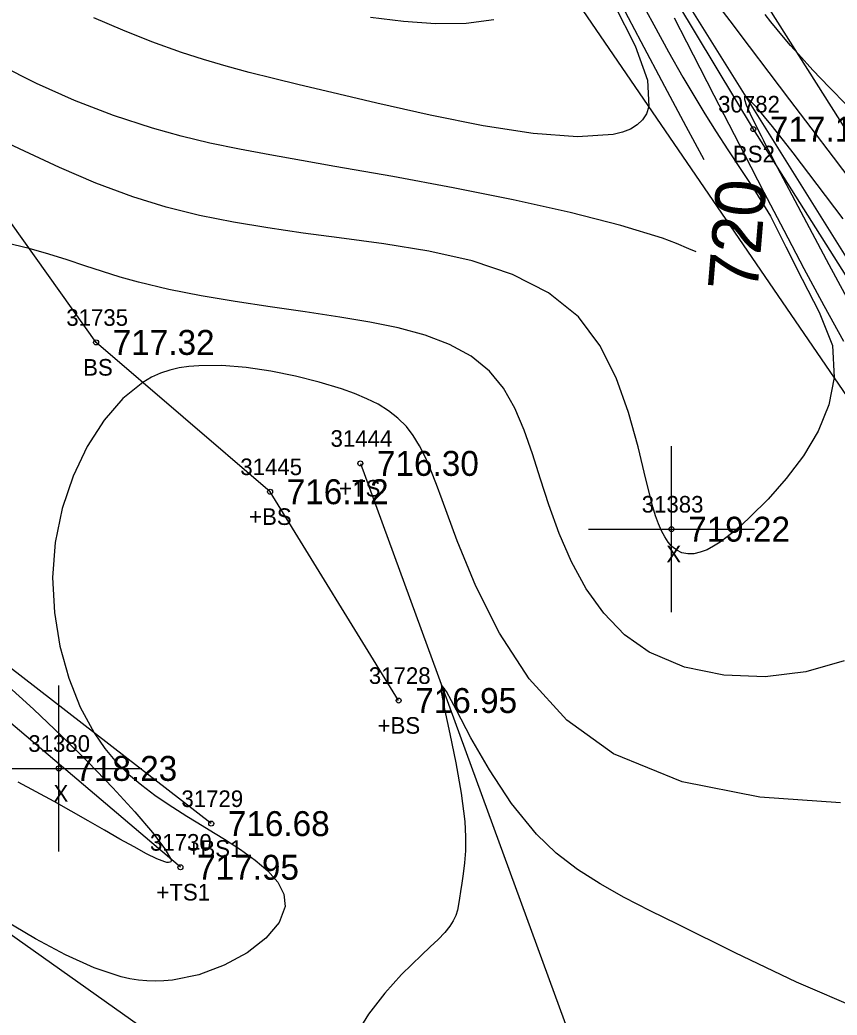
# Model space of a CAD drawing. Extents: x 1376587 to 1378239, y 1000335 to 1003031.
# Drawn here: x 1377060.9 to 1377110.1, y 1001997.9 to 1002057.8 of the extents above; entities that cross this region are included whole.
import ezdxf

# ---------------------------------------------------------------- set-up
doc = ezdxf.new("R2010")
doc.units = 0
for name, color, linetype in [('RD_DTM_BkLn2', 7, 'Continuous'), ('RD_DTM_BkLn_txCode', 7, 'Continuous'), ('RD_DTM_Major1', 7, 'Continuous'), ('RD_DTM_Major1_Lbl', 7, 'Continuous'), ('RD_DTM_Minor1', 7, 'Continuous'), ('RD_EX_H2O', 7, 'Continuous'), ('RD_EX_Misc', 7, 'Continuous'), ('RD_EX_Misc_txCode', 7, 'Continuous'), ('RD_EX_TX_Misc_ELEV', 7, 'Continuous'), ('RD_SMD_Locator', 7, 'Continuous')]:
    doc.layers.add(name, color=color, linetype=linetype)

msp = doc.modelspace()

# ---------------------------------------------------------------- linework, layer by layer
at = {"layer": 'RD_DTM_BkLn2'}
msp.add_line((1377081.372, 1002031.089), (1377098.323, 1001984.744), dxfattribs=at)
for points in [[(1377142.847, 1002000.419), (1377120.857, 1002035.022), (1377093.975, 1002077.46), (1377068.464, 1002119.505), (1377041.306, 1002163.638), (1377022.11, 1002198.969), (1376992.664, 1002247.269), (1376968.66, 1002290.747), (1376938.21, 1002335.497), (1376936.932, 1002336.502), (1376934.733, 1002336.167)], [(1376931.277, 1002334.72), (1376930.538, 1002327.778), (1376948.096, 1002284.738), (1376977.707, 1002235.156), (1376998.585, 1002198.065), (1377023.427, 1002151.701), (1377053.922, 1002110.488), (1377069.919, 1002089.279), (1377076.048, 1002081.264), (1377085.906, 1002071.338), (1377113.825, 1002030.519), (1377124.485, 1002013.092), (1377135.759, 1001990.148)], [(1376935.374, 1002334.231), (1376953.076, 1002295.685), (1376977.004, 1002261.504), (1376998.814, 1002228.831), (1377019.729, 1002192.044), (1377041.392, 1002156.493), (1377062.715, 1002120.197), (1377083.309, 1002087.295), (1377105.033, 1002051.213), (1377126.385, 1002017.412), (1377141.025, 1001985.591), (1377143.73, 1001977.344), (1377160.135, 1001942.462), (1377172.58, 1001925.323), (1377184.431, 1001906.97)], [(1377083.678, 1002016.815), (1377075.938, 1002029.384), (1377065.46, 1002038.372), (1377052.271, 1002056.869), (1377042.811, 1002066.409), (1377033.979, 1002056.948), (1377025.546, 1002060.176), (1377009.284, 1002065.352)], [(1377072.391, 1002009.404), (1377053.266, 1002024.229), (1377030.498, 1002041.755), (1377013.412, 1002051.132)], [(1377070.54, 1002006.776), (1377051.937, 1002022.56), (1377028.67, 1002037.413), (1377011.364, 1002045.988)], [(1377092.351, 1001980.005), (1377043.936, 1002014.334), (1377027.822, 1002012.65)]]:
    msp.add_lwpolyline(points, dxfattribs=at)
at = {"layer": 'RD_DTM_Major1'}
for points in [[(1377096.738, 1002059.39), (1377098.269, 1002056.482), (1377099.693, 1002053.79), (1377100.976, 1002051.381), (1377102.049, 1002049.39)], [(1377101.587, 1002043.829), (1377101.154, 1002044.013), (1377100.415, 1002044.318), (1377099.559, 1002044.641), (1377097.054, 1002045.418), (1377094.001, 1002046.193), (1377090.576, 1002046.95), (1377086.957, 1002047.676), (1377083.319, 1002048.354), (1377079.841, 1002048.97), (1377077.825, 1002049.318), (1377075.915, 1002049.655), (1377074.087, 1002050), (1377072.317, 1002050.37), (1377070.582, 1002050.785), (1377068.858, 1002051.263), (1377066.499, 1002052.038), (1377064.156, 1002052.944), (1377061.867, 1002053.959), (1377059.673, 1002055.063), (1377057.612, 1002056.235), (1377055.725, 1002057.453), (1377055.068, 1002057.919)]]:
    msp.add_lwpolyline(points, dxfattribs=at)
at = {"layer": 'RD_DTM_Minor1'}
for points in [[(1377098.119, 1002059.206), (1377099.038, 1002057.482), (1377099.923, 1002055.868), (1377100.792, 1002054.342), (1377101.453, 1002053.228), (1377102.121, 1002052.137), (1377102.804, 1002051.054), (1377103.508, 1002049.964), (1377104.24, 1002048.851), (1377105.007, 1002047.701), (1377106.067, 1002045.963), (1377106.995, 1002044.133), (1377107.981, 1002042.186), (1377108.995, 1002040.186), (1377109.804, 1002038.186), (1377109.901, 1002036.256), (1377109.579, 1002034.611), (1377108.936, 1002033.034), (1377108.054, 1002031.548), (1377107.02, 1002030.175), (1377105.919, 1002028.939), (1377104.834, 1002027.863), (1377104.353, 1002027.418), (1377103.894, 1002027.017), (1377103.455, 1002026.661), (1377103.035, 1002026.353), (1377102.633, 1002026.097), (1377102.249, 1002025.895), (1377101.838, 1002025.736), (1377101.448, 1002025.651), (1377101.081, 1002025.641), (1377100.737, 1002025.711), (1377100.418, 1002025.861), (1377100.124, 1002026.095), (1377099.902, 1002026.35), (1377099.696, 1002026.663), (1377099.503, 1002027.032), (1377099.322, 1002027.456), (1377099.151, 1002027.934), (1377098.986, 1002028.465), (1377098.556, 1002030.147), (1377098.093, 1002032.086), (1377097.525, 1002034.158), (1377096.784, 1002036.235), (1377095.799, 1002038.193), (1377094.498, 1002039.905), (1377092.695, 1002041.366), (1377090.534, 1002042.467), (1377088.104, 1002043.278), (1377085.494, 1002043.87), (1377082.793, 1002044.311), (1377080.089, 1002044.674), (1377077.924, 1002044.959), (1377075.809, 1002045.262), (1377073.734, 1002045.606), (1377071.692, 1002046.017), (1377069.673, 1002046.517), (1377067.67, 1002047.132), (1377065.448, 1002047.965), (1377063.263, 1002048.902), (1377061.145, 1002049.878), (1377059.122, 1002050.825)], [(1377111.549, 1002047.303), (1377109.863, 1002049.523), (1377108.521, 1002051.29), (1377107.235, 1002052.985), (1377105.997, 1002054.617), (1377104.803, 1002056.194), (1377103.644, 1002057.727), (1377102.515, 1002059.223)], [(1377096.661, 1002058.719), (1377097.929, 1002056.233), (1377098.661, 1002054.153), (1377098.738, 1002052.577), (1377098.597, 1002052.139), (1377098.366, 1002051.77), (1377098.047, 1002051.465), (1377097.643, 1002051.22), (1377097.156, 1002051.032), (1377096.591, 1002050.894), (1377094.449, 1002050.752), (1377091.784, 1002050.953), (1377088.767, 1002051.412), (1377085.568, 1002052.045), (1377082.358, 1002052.767), (1377079.308, 1002053.492), (1377077.68, 1002053.883), (1377076.144, 1002054.259), (1377074.686, 1002054.63), (1377073.288, 1002055.007), (1377071.934, 1002055.402), (1377070.607, 1002055.826), (1377068.82, 1002056.463), (1377067.06, 1002057.164), (1377065.331, 1002057.916)], [(1377089.414, 1002057.8), (1377087.739, 1002057.577), (1377085.901, 1002057.551), (1377083.962, 1002057.684), (1377081.985, 1002057.939)], [(1377100.27, 1002057.918), (1377101.011, 1002056.467), (1377101.81, 1002054.907), (1377102.66, 1002053.249), (1377103.558, 1002051.503), (1377104.498, 1002049.678), (1377105.663, 1002047.425), (1377106.862, 1002045.125), (1377108.075, 1002042.83), (1377109.282, 1002040.59), (1377110.465, 1002038.455)], [(1377110.667, 1002052.657), (1377109.61, 1002053.735), (1377108.624, 1002054.768), (1377107.744, 1002055.723), (1377107.277, 1002056.249), (1377106.853, 1002056.743), (1377106.463, 1002057.212), (1377106.098, 1002057.665), (1377105.748, 1002058.111)], [(1377110.443, 1002045.807), (1377108.887, 1002047.873), (1377107.435, 1002049.776), (1377106.181, 1002051.377), (1377105.216, 1002052.54), (1377104.631, 1002053.127), (1377104.501, 1002053.161), (1377104.499, 1002053.003), (1377104.61, 1002052.669), (1377104.822, 1002052.18), (1377105.122, 1002051.555), (1377105.496, 1002050.812), (1377105.641, 1002050.528), (1377105.794, 1002050.233), (1377105.954, 1002049.925), (1377106.121, 1002049.605), (1377106.296, 1002049.272), (1377106.477, 1002048.927), (1377107.902, 1002046.231), (1377109.588, 1002043.066), (1377111.467, 1002039.566)], [(1377110.5, 1002019.209), (1377108.202, 1002018.542), (1377105.742, 1002018.244), (1377103.257, 1002018.331), (1377100.883, 1002018.817), (1377098.758, 1002019.72), (1377097.276, 1002020.774), (1377096.025, 1002022.068), (1377094.973, 1002023.548), (1377094.092, 1002025.165), (1377093.352, 1002026.864), (1377092.723, 1002028.594), (1377092.22, 1002030.15), (1377091.739, 1002031.66), (1377091.237, 1002033.093), (1377090.668, 1002034.421), (1377089.99, 1002035.613), (1377089.156, 1002036.641), (1377088.05, 1002037.542), (1377086.744, 1002038.253), (1377085.27, 1002038.809), (1377083.658, 1002039.244), (1377081.939, 1002039.593), (1377080.144, 1002039.892), (1377078.052, 1002040.206), (1377075.939, 1002040.514), (1377073.841, 1002040.832), (1377071.795, 1002041.174), (1377069.837, 1002041.555), (1377068.005, 1002041.99), (1377066.901, 1002042.306), (1377065.836, 1002042.641), (1377064.784, 1002042.99), (1377063.717, 1002043.342), (1377062.608, 1002043.69), (1377061.428, 1002044.026), (1377059.473, 1002044.497)], [(1377110.279, 1002010.656), (1377105.43, 1002010.989), (1377100.756, 1002011.92), (1377096.624, 1002013.598), (1377093.806, 1002015.635), (1377091.541, 1002018.117), (1377089.743, 1002020.863), (1377088.327, 1002023.695), (1377087.21, 1002026.431), (1377086.306, 1002028.891), (1377085.96, 1002029.826), (1377085.624, 1002030.678), (1377085.288, 1002031.45), (1377084.937, 1002032.145), (1377084.559, 1002032.764), (1377084.141, 1002033.311), (1377083.636, 1002033.822), (1377083.07, 1002034.263), (1377082.446, 1002034.647), (1377081.763, 1002034.985), (1377081.023, 1002035.289), (1377080.227, 1002035.57), (1377078.891, 1002035.979), (1377077.463, 1002036.344), (1377075.983, 1002036.645), (1377074.493, 1002036.863), (1377073.033, 1002036.978), (1377071.645, 1002036.971), (1377071.041, 1002036.921), (1377070.458, 1002036.833), (1377069.892, 1002036.701), (1377069.34, 1002036.517), (1377068.8, 1002036.274), (1377068.267, 1002035.964), (1377067.072, 1002034.988), (1377065.946, 1002033.682), (1377064.93, 1002032.104), (1377064.07, 1002030.313), (1377063.408, 1002028.365), (1377062.987, 1002026.32), (1377062.838, 1002024.214), (1377062.947, 1002022.119), (1377063.283, 1002020.086), (1377063.814, 1002018.166), (1377064.508, 1002016.412), (1377065.335, 1002014.874), (1377065.994, 1002013.923), (1377066.697, 1002013.092), (1377067.438, 1002012.361), (1377068.208, 1002011.71), (1377069, 1002011.121), (1377069.806, 1002010.574), (1377070.366, 1002010.212), (1377070.93, 1002009.858), (1377071.495, 1002009.508), (1377072.63, 1002008.812), (1377073.198, 1002008.459), (1377074.146, 1002007.848), (1377075.036, 1002007.214), (1377075.809, 1002006.556), (1377076.407, 1002005.87), (1377076.773, 1002005.156), (1377076.846, 1002004.411), (1377076.484, 1002003.458), (1377075.686, 1002002.513), (1377074.549, 1002001.635), (1377073.168, 1002000.881), (1377071.639, 1002000.31), (1377070.058, 1001999.981), (1377069.541, 1001999.934), (1377069.027, 1001999.92), (1377068.515, 1001999.938), (1377068.003, 1001999.987), (1377067.491, 1002000.067), (1377066.975, 1002000.178), (1377065.334, 1002000.714), (1377063.624, 1002001.497), (1377061.819, 1002002.478), (1377059.89, 1002003.606)], [(1377059.971, 1002017.855), (1377061.682, 1002016.304), (1377063.397, 1002014.676), (1377064.981, 1002013.101), (1377066.47, 1002011.552), (1377067.787, 1002010.113), (1377068.857, 1002008.866), (1377069.605, 1002007.892), (1377069.953, 1002007.274), (1377069.97, 1002007.178), (1377069.953, 1002007.112), (1377069.906, 1002007.074), (1377069.829, 1002007.062), (1377069.724, 1002007.073), (1377069.593, 1002007.106), (1377069.122, 1002007.29), (1377068.497, 1002007.595), (1377067.745, 1002007.998), (1377066.891, 1002008.477), (1377065.96, 1002009.01), (1377064.978, 1002009.574), (1377063.966, 1002010.15), (1377062.928, 1002010.732), (1377061.859, 1002011.314), (1377060.76, 1002011.894)], [(1377111.462, 1001998.213), (1377107.641, 1001999.856), (1377103.942, 1002001.629), (1377100.51, 1002003.334), (1377098.832, 1002004.162), (1377097.266, 1002004.96), (1377095.804, 1002005.774), (1377094.44, 1002006.649), (1377093.169, 1002007.631), (1377091.983, 1002008.765), (1377090.472, 1002010.621), (1377089.143, 1002012.634), (1377088.027, 1002014.578), (1377087.152, 1002016.231), (1377086.549, 1002017.365), (1377086.248, 1002017.758), (1377086.245, 1002017.336), (1377086.44, 1002016.29), (1377086.757, 1002014.803), (1377087.118, 1002013.06), (1377087.444, 1002011.243), (1377087.658, 1002009.537), (1377087.706, 1002008.603), (1377087.697, 1002007.774), (1377087.646, 1002007.04), (1377087.569, 1002006.391), (1377087.482, 1002005.818), (1377087.401, 1002005.312), (1377087.341, 1002004.907), (1377087.284, 1002004.539), (1377087.213, 1002004.196), (1377087.113, 1002003.869), (1377086.97, 1002003.548), (1377086.767, 1002003.224), (1377086.452, 1002002.84), (1377086.053, 1002002.428), (1377085.582, 1002001.98), (1377085.05, 1002001.484), (1377084.47, 1002000.932), (1377083.851, 1002000.314), (1377082.844, 1001999.201), (1377081.865, 1001997.932), (1377081.006, 1001996.535)]]:
    msp.add_lwpolyline(points, dxfattribs=at)
at = {"layer": 'RD_EX_H2O'}
msp.add_lwpolyline([(1377136.384, 1001999.335), (1377126.385, 1002017.412), (1377116.954, 1002033.408), (1377090.35, 1002075.98), (1377065.423, 1002117.585), (1377038.304, 1002163.028), (1377017.874, 1002196.373), (1376989.721, 1002244.928), (1376963.62, 1002288.233), (1376935.748, 1002334.332)], dxfattribs=at)
at = {"layer": 'RD_EX_Misc'}
for p, q in [((1377100.109, 1002022.128), (1377100.109, 1002032.128)), ((1377095.109, 1002027.128), (1377105.109, 1002027.128)), ((1377063.21, 1002007.727), (1377063.21, 1002017.727)), ((1377058.21, 1002012.727), (1377068.21, 1002012.727))]:
    msp.add_line(p, q, dxfattribs=at)
at = {"layer": 'RD_SMD_Locator'}
for centre in [(1377105.033, 1002051.213), (1377065.46, 1002038.372), (1377081.372, 1002031.089), (1377075.938, 1002029.384), (1377100.109, 1002027.128), (1377083.678, 1002016.815), (1377063.21, 1002012.727), (1377072.391, 1002009.404), (1377070.54, 1002006.776)]:
    msp.add_circle(centre, 0.15, dxfattribs=at)

# ---------------------------------------------------------------- texts
at = {"layer": 'RD_DTM_BkLn_txCode'}
for s, p in [('30782', (1377102.915, 1002052.213)), ('BS2', (1377103.805, 1002049.213)), ('31735', (1377063.665, 1002039.372)), ('BS', (1377064.68, 1002036.372)), ('31444', (1377079.577, 1002032.089)), ('31445', (1377074.143, 1002030.384)), ('+TS', (1377080.089, 1002029.089)), ('+BS', (1377074.67, 1002027.384)), ('31728', (1377081.883, 1002017.815)), ('+BS', (1377082.41, 1002014.815)), ('31729', (1377070.596, 1002010.404)), ('31730', (1377068.705, 1002007.776)), ('+BS1', (1377070.958, 1002007.404)), ('+TS1', (1377069.091, 1002004.776))]:
    msp.add_text(s, height=1, dxfattribs=at).set_placement(p)
at = {"layer": 'RD_DTM_Major1_Lbl'}
msp.add_text('720', height=3, rotation=85.24963, dxfattribs=at).set_placement((1377105.276, 1002041.382))
at = {"layer": 'RD_EX_Misc_txCode'}
for s, p in [('31383', (1377098.314, 1002028.128)), ('X', (1377099.794, 1002025.128)), ('31380', (1377061.375, 1002013.727)), ('X', (1377062.895, 1002010.727))]:
    msp.add_text(s, height=1, dxfattribs=at).set_placement(p)
at = {"layer": 'RD_EX_TX_Misc_ELEV'}
for s, p in [('717.13', (1377106.033, 1002050.463)), ('717.32', (1377066.46, 1002037.622)), ('716.30', (1377082.372, 1002030.339)), ('716.12', (1377076.938, 1002028.634)), ('719.22', (1377101.109, 1002026.378)), ('716.95', (1377084.678, 1002016.065)), ('718.23', (1377064.21, 1002011.977)), ('716.68', (1377073.391, 1002008.654)), ('717.95', (1377071.54, 1002006.026))]:
    msp.add_text(s, height=1.5, dxfattribs=at).set_placement(p)

doc.saveas('drawing.dxf')
